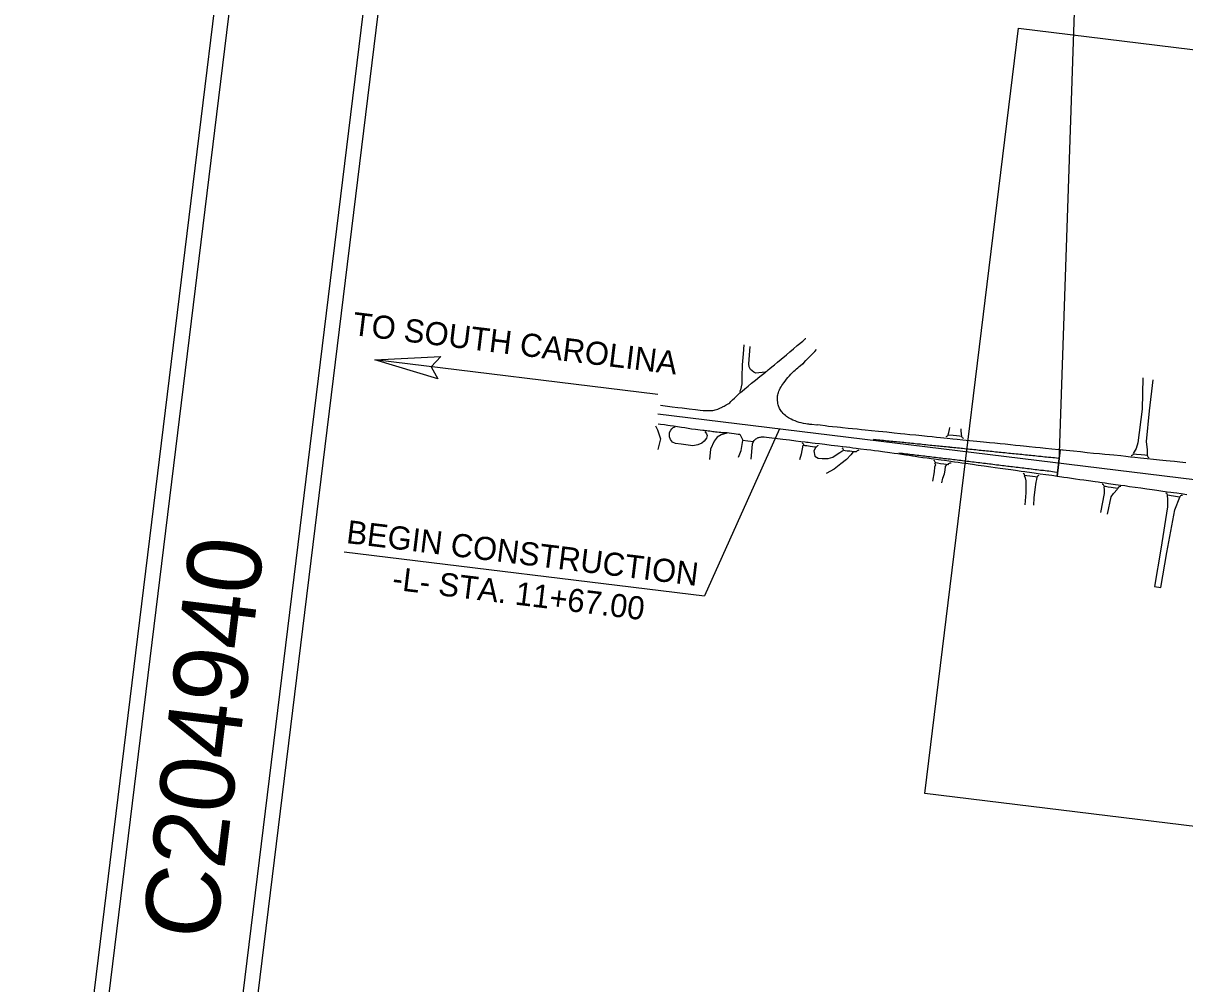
# Model space of a CAD drawing. Extents: x 1756435 to 1766932, y 416863 to 426859.
# Drawn here: x 1759973 to 1761555, y 423307 to 424616 of the extents above; entities that cross this region are included whole.
import ezdxf

# ---------------------------------------------------------------- set-up
doc = ezdxf.new("R2010")
doc.units = 0
for name, color, linetype in [('Exist Roads EOP', 7, 'Continuous'), ('Exist Roads EOP Other', 7, 'Continuous'), ('Exist Roads EOT', 7, 'Continuous'), ('Exist Roads Soil', 7, 'Continuous'), ('Prop EOT', 7, 'Continuous'), ('Prop Horizontal Alignment', 7, 'Continuous'), ('Prop Horizontal Alignment Station Label', 7, 'Continuous'), ('Prop Shade Light', 7, 'Continuous'), ('Prop Terminator CELL', 7, 'Continuous'), ('Sheet Plan CELL', 7, 'Continuous'), ('Sheet Title CELL', 7, 'Continuous')]:
    doc.layers.add(name, color=color, linetype=linetype)

# ---------------------------------------------------------------- blocks, each defined once
blk = doc.blocks.new('Terminator')
at = {"layer": 'Prop Terminator CELL'}
blk.add_lwpolyline([(-9, 1.55), (0, 0), (-9.05, -1.6), (-7.9, 0)], close=True, dxfattribs=at)

msp = doc.modelspace()

# ---------------------------------------------------------------- linework, layer by layer
at = {"layer": 'Exist Roads EOP'}
for points in [[(1760841.4, 424095.2), (1760847.6, 424094.4), (1760857.1, 424093.2), (1760864.8, 424092.2), (1760870.8, 424091.5), (1760880.6, 424090.3), (1760889, 424089.4), (1760895.5, 424088.6), (1760899.3, 424088.2), (1760901.9, 424088), (1760904.6, 424087.9), (1760907.1, 424087.9), (1760909.3, 424087.9), (1760911.2, 424088.1), (1760912.8, 424088.2), (1760914.4, 424088.5), (1760915.9, 424088.9), (1760917.6, 424089.4), (1760919.5, 424090.1), (1760921.4, 424090.9), (1760923.2, 424091.6), (1760924.5, 424092.2), (1760925.2, 424092.6), (1760925.8, 424092.9), (1760926.8, 424093.4), (1760928.1, 424094.1), (1760929.5, 424094.9), (1760930.9, 424095.7), (1760932.6, 424096.7), (1760934.2, 424097.7), (1760935.6, 424098.7), (1760937.2, 424100.1), (1760939.6, 424102.4), (1760942.2, 424104.9), (1760944.5, 424107.2), (1760946.9, 424109.5), (1760949.6, 424111.9), (1760952.8, 424114.6), (1760956.4, 424117.7), (1760960.6, 424121.2), (1760965.3, 424125.1), (1760970.6, 424129.6), (1760976.8, 424134.5), (1760981.9, 424138.6), (1760984.3, 424140.4), (1760985.4, 424141.2), (1760986.6, 424142.1), (1760988.1, 424143.3), (1760990.3, 424145.1), (1760993, 424147.5), (1760996.4, 424150.3), (1761000.6, 424153.8), (1761005.8, 424158.1), (1761012.9, 424164), (1761017.4, 424167.8), (1761022.6, 424172.2), (1761027.7, 424176.4), (1761035, 424182.6), (1761039, 424186.1), (1761039.1, 424186.2)], [(1761034.8, 424151.6), (1761036.4, 424153), (1761039.4, 424156), (1761042.9, 424159.6), (1761046, 424162.8), (1761048.8, 424165.8), (1761051.6, 424168.6), (1761054, 424171)], [(1761557, 424016.9), (1761548.8, 424017.8), (1761541.6, 424018.5), (1761535.6, 424019.1), (1761530.3, 424019.7), (1761521, 424020.6), (1761513, 424021.5), (1761504.4, 424022.3), (1761495.2, 424023.2), (1761487.5, 424024), (1761481.5, 424024.7), (1761475.3, 424025.4), (1761468.4, 424026.1), (1761458.8, 424027), (1761453, 424027.6), (1761446.4, 424028.2), (1761439.1, 424028.9), (1761431.1, 424029.7), (1761422.4, 424030.6), (1761413.3, 424031.6), (1761403.8, 424032.5), (1761394.1, 424033.5), (1761384.1, 424034.6), (1761374.4, 424035.5), (1761365.9, 424036.4), (1761358.6, 424037.2), (1761352.3, 424037.8), (1761343.5, 424038.7), (1761340, 424039), (1761335.8, 424039.5), (1761331.3, 424039.9), (1761325, 424040.6), (1761318, 424041.3), (1761310.9, 424042), (1761303.9, 424042.7), (1761296.8, 424043.5), (1761289.4, 424044.2), (1761281.2, 424045), (1761272.2, 424045.9), (1761262.4, 424046.9), (1761253.2, 424047.8), (1761245.6, 424048.6), (1761239.7, 424049.2), (1761231.9, 424050), (1761222.9, 424051), (1761217.5, 424051.5), (1761211.5, 424052.1), (1761204.7, 424052.8), (1761197.3, 424053.5), (1761189.1, 424054.3), (1761181.1, 424055.1), (1761174.2, 424055.8), (1761168.4, 424056.4), (1761159.4, 424057.4), (1761149.5, 424058.4), (1761144, 424059), (1761138.5, 424059.5), (1761128.7, 424060.5), (1761120.1, 424061.4), (1761115, 424061.9), (1761109.3, 424062.5), (1761102.9, 424063.1), (1761097, 424063.7), (1761089.3, 424064.4), (1761086.3, 424064.8), (1761082, 424065.2), (1761075.8, 424065.8), (1761070.4, 424066.4), (1761065.8, 424067), (1761059, 424067.9), (1761054.6, 424068.5), (1761054.1, 424068.1), (1761047.4, 424068.8), (1761044.7, 424069.1), (1761043.5, 424069.3), (1761041.7, 424069.5), (1761039.3, 424069.9), (1761036.2, 424070.4), (1761033, 424071.1), (1761030.3, 424071.8), (1761027.6, 424072.6), (1761024.6, 424073.8), (1761021.7, 424075), (1761019.3, 424076.2), (1761017.3, 424077.2), (1761015.7, 424078), (1761014.4, 424078.9), (1761013, 424079.9), (1761011.6, 424081.1), (1761010, 424082.6), (1761008.4, 424084.1), (1761007.1, 424085.6), (1761006, 424086.9), (1761005.1, 424088.1), (1761004.3, 424089.3), (1761003.5, 424090.7), (1761002.9, 424092.1), (1761002.5, 424093.2), (1761002.1, 424094.3), (1761001.7, 424095.8), (1761001.3, 424097.5), (1761001, 424099.5), (1761000.7, 424101.6), (1761000.6, 424103.5), (1761000.5, 424105.2), (1761000.6, 424106.6), (1761000.8, 424108), (1761001.1, 424109.5), (1761001.5, 424111.1), (1761002, 424112.8), (1761002.6, 424114.5), (1761003.4, 424116.4), (1761004.4, 424118.3), (1761005.5, 424120.1), (1761006.6, 424121.9), (1761007.8, 424123.7), (1761009.3, 424125.8), (1761011.1, 424128.2), (1761013.1, 424130.7), (1761015, 424133.1), (1761016.9, 424135.4), (1761019, 424137.6), (1761021.1, 424139.7), (1761022.9, 424141.5), (1761024.7, 424143.1), (1761026.6, 424144.8), (1761028.4, 424146.4), (1761030.1, 424147.8), (1761032, 424149.3), (1761034.6, 424151.4), (1761035.3, 424150.5)], [(1760838.1, 424069.8), (1760841.4, 424069.4), (1760846.8, 424068.8), (1760851.2, 424068.2), (1760854.6, 424067.8), (1760859, 424067.2), (1760864.5, 424066.3), (1760869.8, 424065.5), (1760874.6, 424064.8), (1760879.2, 424064.1), (1760883.7, 424063.3), (1760889.1, 424062.6), (1760895.2, 424061.8), (1760899.1, 424061.4), (1760900.9, 424061.2), (1760902.5, 424061), (1760904.3, 424060.7), (1760906.4, 424060.5), (1760908.7, 424060.2), (1760910.9, 424059.9), (1760912.7, 424059.6), (1760914.5, 424059.4), (1760916.2, 424059.2), (1760918.5, 424058.9), (1760921.2, 424058.7), (1760923.1, 424058.4), (1760924.3, 424058.3), (1760926.3, 424058.2), (1760929.3, 424058.1), (1760932.3, 424057.9), (1760935.1, 424057.6), (1760938.1, 424057.2), (1760941.5, 424056.8), (1760944.5, 424056.3), (1760947.1, 424055.7), (1760949.3, 424055.6)], [(1760980.8, 424052.1), (1760982.5, 424052), (1760985.6, 424051.8), (1760989.2, 424051.4), (1760992.9, 424051), (1761000.8, 424050), (1761007.8, 424049.1), (1761016.9, 424048), (1761025.9, 424046.9), (1761032.5, 424046), (1761038.6, 424045.3), (1761040.2, 424045.1), (1761042.4, 424044.8), (1761045, 424044.5), (1761048.1, 424044.1), (1761052.2, 424043.6), (1761057.7, 424042.9), (1761065, 424042.1), (1761074, 424041), (1761082.9, 424039.9), (1761089.6, 424039.1), (1761094.8, 424038.4), (1761099.1, 424037.9), (1761103.3, 424037.4), (1761107.8, 424036.8), (1761113.9, 424036), (1761122.6, 424034.9), (1761127.7, 424034.3), (1761132.9, 424033.6), (1761138.3, 424032.9), (1761143.9, 424032.1), (1761153.5, 424030.8), (1761159.8, 424030), (1761164.7, 424029.3), (1761170, 424028.5), (1761175.3, 424027.7), (1761180.2, 424027), (1761184.5, 424026.3), (1761188.3, 424025.7), (1761192.6, 424025), (1761198.5, 424024.2), (1761204.6, 424023.4), (1761209.9, 424022.6), (1761214.2, 424022.1), (1761217.3, 424021.7), (1761220.2, 424021.3), (1761223.8, 424020.8), (1761228.4, 424020.2), (1761234.3, 424019.4), (1761242, 424018.3), (1761246.7, 424017.7), (1761251.9, 424016.9), (1761257.2, 424016.2), (1761266.4, 424014.9), (1761274, 424013.8), (1761282.1, 424012.7), (1761291.4, 424011.4), (1761297.2, 424010.5), (1761303.9, 424009.6), (1761311.4, 424008.5), (1761318.7, 424007.5), (1761324.7, 424006.7), (1761332.8, 424005.5), (1761337.5, 424004.8), (1761340.5, 424004.4), (1761344.1, 424003.9), (1761350.4, 424003), (1761358.3, 424002), (1761366.2, 424000.9), (1761374.3, 423999.8), (1761382.2, 423998.6), (1761390.9, 423997.4), (1761395.8, 423996.7), (1761401.1, 423995.9), (1761406.7, 423995.2), (1761412.3, 423994.3), (1761418.1, 423993.5), (1761424.1, 423992.7), (1761433.4, 423991.4), (1761437.5, 423990.8), (1761439.6, 423990.5), (1761442.9, 423990), (1761447, 423989.4), (1761451.7, 423988.8), (1761458.1, 423987.9), (1761467.7, 423986.5), (1761473.7, 423985.7), (1761480.3, 423984.7), (1761487.7, 423983.7), (1761495.7, 423982.5), (1761503.7, 423981.4), (1761510.9, 423980.4), (1761517.3, 423979.5), (1761522.9, 423978.7), (1761531.5, 423977.5), (1761536.4, 423976.9), (1761540, 423976.4), (1761544.7, 423975.7), (1761550.6, 423974.9), (1761558.1, 423973.8)]]:
    msp.add_lwpolyline(points, dxfattribs=at)
at = {"layer": 'Exist Roads EOP Other'}
msp.add_line((1760978.8, 424052), (1760980.8, 424052.1), dxfattribs=at)
for points in [[(1760954.9, 424177.7), (1760954.1, 424165.1), (1760952.8, 424150.3), (1760952.1, 424133.9), (1760952, 424124.4), (1760951.4, 424120.1), (1760950.2, 424116.4), (1760948.8, 424113.4)], [(1760984.1, 424140.4), (1760971.4, 424139), (1760968.4, 424140.4), (1760964.1, 424143.8), (1760962.2, 424147.5), (1760961.7, 424151.6), (1760963.3, 424175.1)], [(1761498.5, 424132.5), (1761497.3, 424089.8), (1761491.7, 424044.1), (1761489.2, 424036.2), (1761485.3, 424029.5)], [(1761504.8, 424027.4), (1761504.5, 424034.6), (1761503.1, 424046), (1761507.2, 424087.8), (1761512.5, 424129.7)], [(1760949.3, 424055.6), (1760953.7, 424047.6), (1760960.5, 424046.8), (1760967.8, 424046), (1760969, 424047.3)], [(1761254.2, 424049.8), (1761253.5, 424050.3), (1761252.8, 424050.8), (1761252.3, 424051.5), (1761251.9, 424052.3), (1761251.8, 424052.8), (1761248.8, 424053.1), (1761244.7, 424053.4), (1761240, 424053.8), (1761232.9, 424054.5), (1761232.6, 424054.2), (1761232.2, 424053.5), (1761231.6, 424052.9), (1761230.8, 424052.5), (1761229.9, 424052.2)], [(1761034.5, 424043.8), (1761035.1, 424043.3), (1761035.9, 424042.4), (1761036.2, 424041.7), (1761036.4, 424040.8), (1761038, 424040.6), (1761040.7, 424040.2), (1761045, 424039.6), (1761048.2, 424039.2), (1761051.5, 424038.7), (1761053.9, 424038.5), (1761054.6, 424039.6), (1761055.2, 424040.1), (1761055.7, 424040.6), (1761056.5, 424040.8)], [(1761088.5, 424037.2), (1761089.1, 424036.7), (1761089.6, 424036), (1761090.1, 424034.9), (1761090.4, 424034), (1761091, 424034), (1761093.1, 424033.6), (1761095.8, 424033.3), (1761099.2, 424032.9), (1761102, 424032.5), (1761104.4, 424032.3), (1761108.5, 424032.1), (1761109.2, 424032.9), (1761109.7, 424033.5), (1761110.4, 424033.9), (1761111.1, 424034.2), (1761112.1, 424034.4)], [(1761482.3, 424026.6), (1761483.2, 424026.8), (1761484, 424027.1), (1761484.7, 424027.6), (1761485.2, 424028.3), (1761485.8, 424029.2), (1761489.7, 424028.7), (1761496.2, 424028.1), (1761500.9, 424027.6), (1761504.1, 424027.2), (1761504.7, 424025.8), (1761505.2, 424025.1), (1761505.8, 424024.5), (1761506.6, 424024.1)], [(1761213.3, 424020.4), (1761214, 424019.8), (1761214.6, 424019.2), (1761215.1, 424018.4), (1761215.3, 424017.2), (1761218.7, 424016.7), (1761222.9, 424016), (1761227.3, 424015.4), (1761230.4, 424015), (1761233.1, 424014.7), (1761233.9, 424015.8), (1761235, 424016.5), (1761235.8, 424016.9), (1761237.1, 424017)], [(1761335.4, 424003.1), (1761336, 424002.4), (1761336.5, 424001.7), (1761336.9, 424000.8), (1761337.1, 424000.1), (1761340.5, 423999.6), (1761344.2, 423999.1), (1761347.9, 423998.6), (1761351.5, 423998), (1761354.6, 423997.6), (1761354.9, 423998.3), (1761355.5, 423999), (1761356.1, 423999.7), (1761356.9, 424000.1)], [(1761336.7, 423999.6), (1761337.9, 423996.4), (1761338.8, 423992.2), (1761338.9, 423987.4), (1761339, 423976.1), (1761337.6, 423959.5)], [(1761349.8, 423959), (1761350.5, 423969.3), (1761351.5, 423980.4), (1761352.9, 423990.4), (1761353.8, 423994), (1761354.6, 423997.1)], [(1761445.4, 423984.3), (1761445.7, 423980), (1761445.8, 423974.9), (1761440.5, 423949)], [(1761468.2, 423984.5), (1761467.5, 423984.6), (1761466.3, 423984.3), (1761465.3, 423983.5), (1761463.6, 423981.8), (1761455.3, 423983.2), (1761451, 423983.8), (1761447.5, 423984.4), (1761445.9, 423984.6), (1761445.6, 423985.2), (1761445.2, 423986), (1761444.6, 423986.8), (1761444, 423987.4), (1761443.4, 423988)], [(1761450.1, 423946.9), (1761455.1, 423970.3), (1761458.4, 423974.9), (1761464, 423981.1)], [(1761552.2, 423972.5), (1761551.2, 423972.5), (1761550.4, 423972.1), (1761549.7, 423971.7), (1761549.1, 423971), (1761548.8, 423970.6), (1761548.3, 423970), (1761545.6, 423970.4), (1761542.7, 423970.9), (1761539.9, 423971.3), (1761537, 423971.7), (1761534.6, 423972.1), (1761531.8, 423972.6), (1761531.7, 423973.1), (1761531.4, 423974.1), (1761530.8, 423974.8), (1761530.2, 423975.5), (1761529.7, 423975.8)], [(1761531.4, 423972.2), (1761531.8, 423967.2), (1761531.7, 423957)], [(1761541.8, 423952.8), (1761548.9, 423970.1)], [(1761531.7, 423957), (1761522.9, 423899), (1761514.3, 423848.4), (1761523, 423846.8), (1761531.1, 423894.8), (1761541.8, 423952.8)]]:
    msp.add_lwpolyline(points, dxfattribs=at)
msp.add_spline([(1760969, 424047.3), (1760970.5, 424048.6), (1760972.4, 424050.1), (1760974.5, 424051.1), (1760976.5, 424051.8), (1760978.8, 424052)], degree=3, dxfattribs=at)
at = {"layer": 'Exist Roads EOT'}
for points in [[(1761384.5, 424022.7), (1761380.6, 424023.1), (1761378.1, 424023.4), (1761375.6, 424023.6), (1761373.1, 424023.9), (1761370.6, 424024.1), (1761369.7, 424024.2), (1761367.2, 424024.5), (1761364.7, 424024.7), (1761362.2, 424025), (1761359.7, 424025.2), (1761357.2, 424025.5), (1761356.2, 424025.6), (1761353.7, 424025.8), (1761351.2, 424026.1), (1761348.7, 424026.3), (1761346.2, 424026.6), (1761343.7, 424026.8), (1761341.2, 424027.1), (1761340.8, 424027.1), (1761338.3, 424027.4), (1761335.9, 424027.6), (1761333.4, 424027.9), (1761330.9, 424028.1), (1761328.4, 424028.4), (1761325.9, 424028.6), (1761325.6, 424028.7), (1761323.1, 424028.9), (1761320.6, 424029.2), (1761318.1, 424029.4), (1761315.6, 424029.7), (1761313.1, 424029.9), (1761310.7, 424030.2), (1761310.2, 424030.2), (1761307.7, 424030.5), (1761305.2, 424030.7), (1761302.8, 424031), (1761300.3, 424031.2), (1761297.8, 424031.5), (1761295.4, 424031.7), (1761292.9, 424032), (1761290.4, 424032.2), (1761288, 424032.5), (1761285.5, 424032.7), (1761283, 424033), (1761280.6, 424033.2), (1761278.1, 424033.5), (1761275.6, 424033.8), (1761273.2, 424034), (1761270.7, 424034.3), (1761268.2, 424034.5), (1761265.7, 424034.8), (1761265.2, 424034.9), (1761262.7, 424035.1), (1761260.2, 424035.4), (1761257.7, 424035.6), (1761255.2, 424035.9), (1761252.8, 424036.1), (1761250.9, 424036.3), (1761248.4, 424036.6), (1761245.9, 424036.8), (1761243.4, 424037.1), (1761241, 424037.3), (1761238.5, 424037.6), (1761236, 424037.8), (1761235.3, 424037.9), (1761232.8, 424038.1), (1761230.4, 424038.4), (1761227.9, 424038.7), (1761225.4, 424038.9), (1761222.9, 424039.2), (1761221, 424039.4), (1761218.5, 424039.7), (1761216, 424039.9), (1761213.5, 424040.1), (1761211.1, 424040.4), (1761208.6, 424040.6), (1761206.1, 424040.9), (1761205.3, 424041), (1761202.8, 424041.2), (1761200.3, 424041.5), (1761197.9, 424041.7), (1761195.4, 424042), (1761192.9, 424042.2), (1761190.8, 424042.4), (1761188.3, 424042.7), (1761185.8, 424043), (1761183.3, 424043.2), (1761180.9, 424043.5), (1761178.4, 424043.7), (1761175.9, 424044), (1761175.2, 424044), (1761172.8, 424044.3), (1761170.3, 424044.5), (1761167.8, 424044.8), (1761165.3, 424045), (1761162.8, 424045.2), (1761160.3, 424045.5), (1761160.1, 424045.5), (1761157.7, 424045.8), (1761155.2, 424046), (1761152.7, 424046.3), (1761150.2, 424046.5), (1761147.7, 424046.8), (1761145.2, 424047.1), (1761142.8, 424047.3), (1761140.3, 424047.5), (1761137.8, 424047.8), (1761135.3, 424048), (1761132.8, 424048.3), (1761131.4, 424048.4)], [(1761165.9, 424030.4), (1761168.4, 424030.1), (1761170.8, 424029.8), (1761173.3, 424029.5), (1761175.8, 424029.2), (1761178.3, 424028.9), (1761180.8, 424028.6), (1761180.9, 424028.6), (1761183.4, 424028.3), (1761185.9, 424028), (1761188.3, 424027.7), (1761190.8, 424027.4), (1761193.3, 424027.1), (1761195.8, 424026.8), (1761196.2, 424026.8), (1761198.7, 424026.5), (1761201.2, 424026.2), (1761203.6, 424025.9), (1761206.1, 424025.6), (1761208.6, 424025.3), (1761211.1, 424025), (1761213.6, 424024.7), (1761216, 424024.4), (1761218.5, 424024.1), (1761221, 424023.7), (1761223.5, 424023.4), (1761225.9, 424023.2), (1761228.4, 424022.9), (1761230.8, 424022.6), (1761233.3, 424022.3), (1761235.8, 424022), (1761238.3, 424021.7), (1761240.4, 424021.4), (1761242.9, 424021.1), (1761245.4, 424020.8), (1761247.9, 424020.5), (1761250.3, 424020.2), (1761252.8, 424019.9), (1761255.3, 424019.6), (1761256.2, 424019.5), (1761258.7, 424019.2), (1761261.2, 424018.9), (1761263.6, 424018.6), (1761266.1, 424018.3), (1761268.6, 424018), (1761271.1, 424017.7), (1761271.5, 424017.7), (1761273.9, 424017.4), (1761276.4, 424017.1), (1761278.9, 424016.8), (1761281.4, 424016.5), (1761283.9, 424016.2), (1761286.3, 424015.9), (1761286.8, 424015.8), (1761289.3, 424015.5), (1761291.8, 424015.2), (1761294.2, 424014.9), (1761296.7, 424014.5), (1761299.2, 424014.2), (1761301.7, 424013.9), (1761302, 424013.9), (1761304.5, 424013.6), (1761307, 424013.3), (1761309.5, 424013), (1761311.9, 424012.7), (1761314.4, 424012.4), (1761316.1, 424012.2), (1761318.5, 424011.9), (1761321, 424011.6), (1761323.5, 424011.3), (1761326, 424011), (1761328.5, 424010.7), (1761330.9, 424010.4), (1761331.3, 424010.3), (1761333.8, 424010.1), (1761336.3, 424009.8), (1761338.7, 424009.5), (1761341.2, 424009.2), (1761343.7, 424008.9), (1761346.2, 424008.6), (1761346.5, 424008.5), (1761349, 424008.2), (1761351.5, 424007.9), (1761354, 424007.6), (1761356.5, 424007.3), (1761358.9, 424007), (1761360.4, 424006.9), (1761362.9, 424006.6), (1761365.4, 424006.3), (1761367.8, 424006), (1761370.3, 424005.7), (1761372.8, 424005.3), (1761375.3, 424005), (1761375.5, 424005), (1761378, 424004.7), (1761382.2, 424004.2)]]:
    msp.add_lwpolyline(points, dxfattribs=at)
at = {"layer": 'Exist Roads Soil'}
for points in [[(1760834.7, 424067.3), (1760837.3, 424061.7), (1760841.2, 424049.4), (1760837.8, 424035)], [(1760901.7, 424059.6), (1760904.1, 424056.5), (1760904.8, 424053.8), (1760903.8, 424050.2), (1760900.6, 424046.4), (1760897.5, 424043.4), (1760892.4, 424041.1), (1760885.4, 424040), (1760869.6, 424042.3), (1760861.7, 424043), (1760857.7, 424045), (1760854.9, 424048.5), (1760853.6, 424052), (1760853.7, 424057.9), (1760855.3, 424061.2), (1760857, 424063.3), (1760858.7, 424064.7), (1760861.2, 424065.9)], [(1760931.8, 424057.2), (1760924, 424054.7), (1760918.7, 424051.7), (1760914.5, 424046.5), (1760909.6, 424035.3), (1760908.3, 424021.2)], [(1761233.1, 424055.5), (1761233.9, 424058.2), (1761234.9, 424062.2), (1761235.4, 424064.7)], [(1761251.7, 424053.1), (1761251.3, 424056), (1761251, 424060.6), (1761250.9, 424063.2)], [(1760947.8, 424024.7), (1760951.3, 424033.5), (1760953.7, 424047.4)], [(1760967.4, 424045.6), (1760966.1, 424042), (1760964.6, 424021.6)], [(1761035.2, 424040.8), (1761033.1, 424028.6), (1761030.5, 424020.7)], [(1761052.7, 424038.3), (1761050.3, 424033.3), (1761051.7, 424025.8), (1761055.9, 424023.3), (1761061.7, 424022.7), (1761069.5, 424022.6), (1761075.9, 424024.3), (1761080.7, 424027.7), (1761085.5, 424030.9), (1761089.5, 424033.8)], [(1761103.7, 424031.8), (1761100.4, 424027.8), (1761094.7, 424021.3), (1761086.8, 424015.4), (1761077.9, 424008.3), (1761067, 424002.4)], [(1761214.7, 424016.9), (1761215.9, 424013.9), (1761214.7, 424010.8), (1761213.9, 424004.3), (1761211.8, 423991.8)], [(1761224.5, 423989.6), (1761226.1, 423996.1), (1761228.1, 424001.7), (1761229, 424006.8), (1761229.7, 424011.7), (1761230.7, 424013.5), (1761231.7, 424014.7)]]:
    msp.add_lwpolyline(points, dxfattribs=at)
at = {"layer": 'Prop EOT'}
msp.add_line((1761381.6, 423998.7), (1761385.9, 424034.4), dxfattribs=at)
at = {"layer": 'Prop Horizontal Alignment'}
msp.add_line((1760837.8, 424083.4), (1762954.6, 423824.4), dxfattribs=at)
at = {"layer": 'Prop Horizontal Alignment Station Label'}
for p in [(1761003.6, 424063.1), (1760410.6, 423895.4)]:
    msp.add_line(p, (1760901.1, 423835.4), dxfattribs=at)
msp.add_lwpolyline([(1760495, 424768.9), (1761405.6, 424657.5), (1761383.8, 424016.6)], dxfattribs=at)
at = {"layer": 'Prop Shade Light'}
msp.add_line((1761385.9, 424034.4), (1761381.6, 423998.7), dxfattribs=at)
for points in [[(1761557, 424016.9), (1761548.8, 424017.8), (1761541.6, 424018.5), (1761535.6, 424019.1), (1761530.3, 424019.7), (1761521, 424020.6), (1761513, 424021.5), (1761504.4, 424022.3), (1761495.2, 424023.2), (1761487.5, 424024), (1761481.5, 424024.7), (1761475.3, 424025.4), (1761468.4, 424026.1), (1761458.8, 424027), (1761453, 424027.6), (1761446.4, 424028.2), (1761439.1, 424028.9), (1761431.1, 424029.7), (1761422.4, 424030.6), (1761413.3, 424031.6), (1761403.8, 424032.5), (1761394.1, 424033.5), (1761385.9, 424034.4)], [(1761381.6, 423998.7), (1761382.2, 423998.6), (1761390.9, 423997.4), (1761395.8, 423996.7), (1761401.1, 423995.9), (1761406.7, 423995.2), (1761412.3, 423994.3), (1761418.1, 423993.5), (1761424.1, 423992.7), (1761433.4, 423991.4), (1761437.5, 423990.8), (1761439.6, 423990.5), (1761442.9, 423990), (1761447, 423989.4), (1761451.7, 423988.8), (1761458.1, 423987.9), (1761467.7, 423986.5), (1761473.7, 423985.7), (1761480.3, 423984.7), (1761487.7, 423983.7), (1761495.7, 423982.5), (1761503.7, 423981.4), (1761510.9, 423980.4), (1761517.3, 423979.5), (1761522.9, 423978.7), (1761531.5, 423977.5), (1761536.4, 423976.9), (1761540, 423976.4), (1761544.7, 423975.7), (1761550.6, 423974.9), (1761558.1, 423973.8)]]:
    msp.add_lwpolyline(points, dxfattribs=at)
at = {"layer": 'Sheet Plan CELL'}
msp.add_line((1760837.9, 424109.7), (1760452.3, 424156.9), dxfattribs=at)
msp.add_lwpolyline([(1761201.5, 423566.5), (1761329, 424608.7), (1762817.9, 424426.5), (1762690.4, 423384.3)], close=True, dxfattribs=at)
at = {"layer": 'Sheet Title CELL'}
for p, q in [((1760176.2, 422503.6), (1760676.5, 426591.9)), ((1760287, 423242.7), (1760696.5, 426589.4))]:
    msp.add_line(p, q, dxfattribs=at)
for points in [[(1760478.5, 426636.5), (1759973.3, 422508.1)], [(1760478.5, 426636.5), (1759973.3, 422508.1)], [(1760496.2, 426614), (1759995.8, 422525.7)]]:
    msp.add_lwpolyline(points, dxfattribs=at)

# ---------------------------------------------------------------- block references
at = {"layer": 'Sheet Plan CELL', "xscale": 9.789102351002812, "yscale": 9.789102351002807, "rotation": 173.02339854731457}
msp.add_blockref('Terminator', (1760452.3, 424156.9), dxfattribs=at)

# ---------------------------------------------------------------- texts
at = {"layer": 'Sheet Plan CELL'}
for s, rotation, p in [('TO SOUTH CAROLINA', 353.0234, (1760420.8, 424191)), ('BEGIN CONSTRUCTION', 353.0244, (1760412.4, 423907.6)), ('-L- STA. 11+67.00', 353.0244, (1760474.8, 423844.3))]:
    msp.add_text(s, height=31.5, rotation=rotation, dxfattribs=at).set_placement(p)
at = {"layer": 'Sheet Title CELL'}
msp.add_text('C204940', height=100.95, rotation=83.0234, dxfattribs=at).set_placement((1760235.2, 423364.5))

doc.saveas('drawing.dxf')
